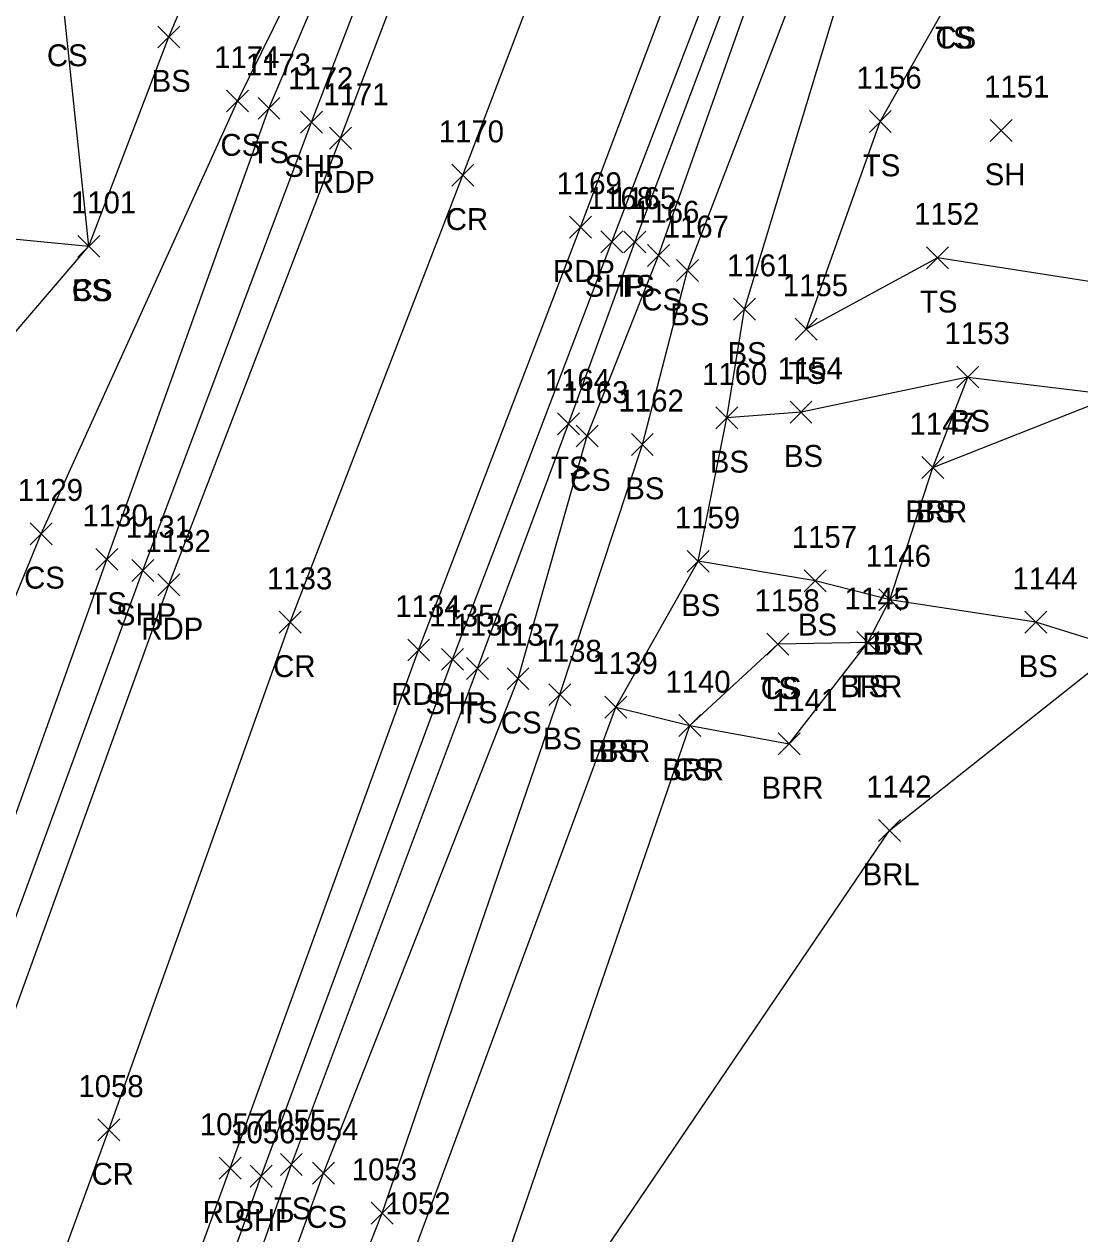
# Model space of a CAD drawing. Extents: x 1554917 to 1555870, y 813367 to 816333.
# Drawn here: x 1555006.4 to 1555102.6, y 813476.5 to 813586.9 of the extents above; entities that cross this region are included whole.
import ezdxf

# ---------------------------------------------------------------- set-up
doc = ezdxf.new("R2010")
doc.units = 0
for name, color, linetype in [('L_A', 7, 'Continuous'), ('L_I', 7, 'Continuous'), ('L_TIC', 7, 'Continuous'), ('LABL', 7, 'Continuous'), ('LELB', 7, 'Continuous'), ('P_A', 7, 'Continuous'), ('P_I', 7, 'Continuous'), ('P_TIC', 7, 'Continuous'), ('PET', 7, 'Continuous'), ('PRC', 7, 'Continuous'), ('PSP', 7, 'Continuous')]:
    doc.layers.add(name, color=color, linetype=linetype)

msp = doc.modelspace()

# ---------------------------------------------------------------- linework, layer by layer
at = {"layer": 'L_TIC'}
for points in [[(1555018.54, 813584.69), (1555020.54, 813586.69)], [(1555020.54, 813584.69), (1555018.54, 813586.69)], [(1555024.82, 813578.85), (1555026.82, 813580.85)], [(1555026.82, 813578.85), (1555024.82, 813580.85)], [(1555027.68, 813578.18), (1555029.68, 813580.18)], [(1555029.68, 813578.18), (1555027.68, 813580.18)], [(1555083.43, 813576.98), (1555085.43, 813578.98)], [(1555085.43, 813576.98), (1555083.43, 813578.98)], [(1555094.46, 813576.17), (1555096.46, 813578.17)], [(1555096.46, 813576.17), (1555094.46, 813578.17)], [(1555011.26, 813565.6), (1555013.26, 813567.6)], [(1555013.26, 813565.6), (1555011.26, 813567.6)], [(1555011.26, 813565.6), (1555013.26, 813567.6)], [(1555013.26, 813565.6), (1555011.26, 813567.6)], [(1555061.05, 813565.99), (1555063.05, 813567.99)], [(1555063.05, 813565.99), (1555061.05, 813567.99)], [(1555063.2, 813564.75), (1555065.2, 813566.75)], [(1555065.2, 813564.75), (1555063.2, 813566.75)], [(1555088.64, 813564.56), (1555090.64, 813566.56)], [(1555090.64, 813564.56), (1555088.64, 813566.56)], [(1555065.84, 813563.4), (1555067.84, 813565.4)], [(1555067.84, 813563.4), (1555065.84, 813565.4)], [(1555071.05, 813559.86), (1555073.05, 813561.86)], [(1555073.05, 813559.86), (1555071.05, 813561.86)], [(1555076.66, 813558.05), (1555078.66, 813560.05)], [(1555078.66, 813558.05), (1555076.66, 813560.05)], [(1555091.42, 813553.68), (1555093.42, 813555.68)], [(1555093.42, 813553.68), (1555091.42, 813555.68)], [(1555069.43, 813549.96), (1555071.43, 813551.96)], [(1555071.43, 813549.96), (1555069.43, 813551.96)], [(1555069.43, 813549.96), (1555071.43, 813551.96)], [(1555071.43, 813549.96), (1555069.43, 813551.96)], [(1555076.2, 813550.48), (1555078.2, 813552.48)], [(1555078.2, 813550.48), (1555076.2, 813552.48)], [(1555055, 813549.42), (1555057, 813551.42)], [(1555057, 813549.42), (1555055, 813551.42)], [(1555056.7, 813548.3), (1555058.7, 813550.3)], [(1555058.7, 813548.3), (1555056.7, 813550.3)], [(1555061.73, 813547.53), (1555063.73, 813549.53)], [(1555063.73, 813547.53), (1555061.73, 813549.53)], [(1555088.23, 813545.42), (1555090.23, 813547.42)], [(1555090.23, 813545.42), (1555088.23, 813547.42)], [(1555088.23, 813545.42), (1555090.23, 813547.42)], [(1555090.23, 813545.42), (1555088.23, 813547.42)], [(1555006.9, 813539.38), (1555008.9, 813541.38)], [(1555008.9, 813539.38), (1555006.9, 813541.38)], [(1555012.89, 813537.05), (1555014.89, 813539.05)], [(1555014.89, 813537.05), (1555012.89, 813539.05)], [(1555066.83, 813536.87), (1555068.83, 813538.87)], [(1555068.83, 813536.87), (1555066.83, 813538.87)], [(1555066.83, 813536.87), (1555068.83, 813538.87)], [(1555068.83, 813536.87), (1555066.83, 813538.87)], [(1555077.48, 813535.1), (1555079.48, 813537.1)], [(1555079.48, 813535.1), (1555077.48, 813537.1)], [(1555084.29, 813533.37), (1555086.29, 813535.37)], [(1555086.29, 813533.37), (1555084.29, 813535.37)], [(1555084.29, 813533.37), (1555086.29, 813535.37)], [(1555086.29, 813533.37), (1555084.29, 813535.37)], [(1555097.61, 813531.31), (1555099.61, 813533.31)], [(1555099.61, 813531.31), (1555097.61, 813533.31)], [(1555074.09, 813529.31), (1555076.09, 813531.31)], [(1555076.09, 813529.31), (1555074.09, 813531.31)], [(1555074.09, 813529.31), (1555076.09, 813531.31)], [(1555076.09, 813529.31), (1555074.09, 813531.31)], [(1555082.3, 813529.48), (1555084.3, 813531.48)], [(1555084.3, 813529.48), (1555082.3, 813531.48)], [(1555082.3, 813529.48), (1555084.3, 813531.48)], [(1555084.3, 813529.48), (1555082.3, 813531.48)], [(1555046.7, 813527.1), (1555048.7, 813529.1)], [(1555048.7, 813527.1), (1555046.7, 813529.1)], [(1555050.39, 813526.17), (1555052.39, 813528.17)], [(1555052.39, 813526.17), (1555050.39, 813528.17)], [(1555054.21, 813524.71), (1555056.21, 813526.71)], [(1555056.21, 813524.71), (1555054.21, 813526.71)], [(1555059.32, 813523.58), (1555061.32, 813525.58)], [(1555061.32, 813523.58), (1555059.32, 813525.58)], [(1555059.32, 813523.58), (1555061.32, 813525.58)], [(1555061.32, 813523.58), (1555059.32, 813525.58)], [(1555066.05, 813521.89), (1555068.05, 813523.89)], [(1555068.05, 813521.89), (1555066.05, 813523.89)], [(1555066.05, 813521.89), (1555068.05, 813523.89)], [(1555068.05, 813521.89), (1555066.05, 813523.89)], [(1555075.12, 813520.23), (1555077.12, 813522.23)], [(1555077.12, 813520.23), (1555075.12, 813522.23)], [(1555084.28, 813512.33), (1555086.28, 813514.33)], [(1555086.28, 813512.33), (1555084.28, 813514.33)], [(1555029.72, 813481.86), (1555031.72, 813483.86)], [(1555031.72, 813481.86), (1555029.72, 813483.86)], [(1555032.65, 813481.08), (1555034.65, 813483.08)], [(1555034.65, 813481.08), (1555032.65, 813483.08)], [(1555038.01, 813477.41), (1555040.01, 813479.41)], [(1555040.01, 813477.41), (1555038.01, 813479.41)]]:
    msp.add_lwpolyline(points, dxfattribs=at)
at = {"layer": 'LABL'}
for points in [[(1555021.43, 813420.92), (1555042.06, 813475.32), (1555060.32, 813524.58), (1555067.05, 813522.89), (1555076.12, 813521.23), (1555083.3, 813530.48), (1555085.29, 813534.37), (1555089.23, 813546.42), (1555105.94, 813553.01)], [(1555021.43, 813420.92), (1555032.42, 813420.89), (1555053.86, 813467), (1555085.28, 813513.33), (1555106.23, 813529.94), (1555105.94, 813553.01)]]:
    msp.add_lwpolyline(points, dxfattribs=at)
at = {"layer": 'LELB'}
for points in [[(1554960.86, 813387.22), (1554975.88, 813430.61), (1554997.67, 813492.71), (1555013.89, 813538.05), (1555028.68, 813579.18), (1555048.82, 813626.54), (1555068.18, 813674.18), (1555096.05, 813749.22), (1555111.01, 813785.1), (1555115.51, 813798.83), (1555119.3, 813812.87), (1555134.87, 813853.17), (1555141.95, 813870.8), (1555155.34, 813907.69), (1555153.32, 813917.67), (1555161.57, 813925.65), (1555168.92, 813938.89)], [(1554992.4, 813377.01), (1555009.62, 813423.34), (1555030.72, 813482.86), (1555047.7, 813528.1), (1555056, 813550.42), (1555062.05, 813566.99), (1555080.33, 813615.57), (1555099.41, 813662.25), (1555114.13, 813700.62), (1555127, 813733.84), (1555152.94, 813799.24), (1555168.16, 813840.25), (1555187.47, 813890.8), (1555199.5, 813919.6)], [(1554997.34, 813375.96), (1555001.03, 813380.2), (1555008.26, 813399.3), (1555016.85, 813422.36), (1555039.01, 813478.41), (1555055.21, 813525.71), (1555062.73, 813548.53), (1555066.84, 813564.4), (1555085.89, 813613.91), (1555101.8, 813661.36), (1555117.2, 813700.9), (1555129.69, 813732.82), (1555155.55, 813797.61), (1555171.4, 813838.65), (1555190.74, 813889.78), (1555201.42, 813914.42), (1555204.39, 813917.83), (1555206.44, 813916.94)], [(1555060.32, 813524.58), (1555067.83, 813537.87), (1555070.43, 813550.96), (1555072.05, 813560.86), (1555087.88, 813613.15), (1555106.35, 813658.95), (1555120.2, 813700.04), (1555133.19, 813731.1), (1555158.65, 813797.07), (1555174.38, 813837.99), (1555194.21, 813888.82), (1555206.44, 813916.94)], [(1554994.08, 813375.71), (1555012.26, 813423.24), (1555033.65, 813482.08), (1555051.39, 813527.17), (1555057.7, 813549.3), (1555064.2, 813565.75), (1555082.14, 813616.42), (1555099.41, 813662.25)], [(1554955.97, 813389.51), (1554961.01, 813406.77), (1554970.65, 813432.6), (1554989.8, 813496.28), (1555007.9, 813540.38), (1555025.82, 813579.85), (1555048.82, 813626.54)], [(1554928.52, 813569.72), (1554947.56, 813564.37), (1554964.46, 813556.66), (1554984.28, 813565), (1554997.17, 813568.08), (1555012.26, 813566.6), (1555009.99, 813588.02), (1555015.55, 813603.36), (1555029.3, 813621.81)], [(1555104.83, 813563.19), (1555089.64, 813565.56), (1555077.66, 813559.05), (1555084.43, 813577.98), (1555091.02, 813589.64), (1555101.22, 813603.84)], [(1554957.39, 813409.71), (1554960.72, 813434.3), (1554980.97, 813500.69), (1554989.73, 813523.17), (1554992.08, 813531.74), (1554995.75, 813541.57), (1554998.43, 813550.46), (1555012.26, 813566.6), (1555019.54, 813585.69), (1555024.77, 813597.99)], [(1555089.23, 813546.42), (1555092.42, 813554.68), (1555077.2, 813551.48), (1555070.43, 813550.96)], [(1555092.42, 813554.68), (1555105.94, 813553.01)], [(1555106.23, 813529.94), (1555098.61, 813532.31), (1555085.29, 813534.37), (1555078.48, 813536.1), (1555067.83, 813537.87)], [(1555004.95, 813373.58), (1555018.35, 813396.09), (1555032.42, 813420.89), (1555049, 813470.38), (1555067.05, 813522.89), (1555075.09, 813530.31)], [(1555083.3, 813530.48), (1555075.09, 813530.31)]]:
    msp.add_lwpolyline(points, dxfattribs=at)
at = {"layer": 'P_TIC'}
for points in [[(1555031.55, 813576.93), (1555033.55, 813578.93)], [(1555033.55, 813576.93), (1555031.55, 813578.93)], [(1555034.2, 813575.47), (1555036.2, 813577.47)], [(1555036.2, 813575.47), (1555034.2, 813577.47)], [(1555045.37, 813572.08), (1555047.37, 813574.08)], [(1555047.37, 813572.08), (1555045.37, 813574.08)], [(1555056.09, 813567.35), (1555058.09, 813569.35)], [(1555058.09, 813567.35), (1555056.09, 813569.35)], [(1555058.94, 813566), (1555060.94, 813568)], [(1555060.94, 813566), (1555058.94, 813568)], [(1555016.18, 813536.03), (1555018.18, 813538.03)], [(1555018.18, 813536.03), (1555016.18, 813538.03)], [(1555018.55, 813534.73), (1555020.55, 813536.73)], [(1555020.55, 813534.73), (1555018.55, 813536.73)], [(1555029.62, 813531.31), (1555031.62, 813533.31)], [(1555031.62, 813531.31), (1555029.62, 813533.31)], [(1555041.33, 813528.78), (1555043.33, 813530.78)], [(1555043.33, 813528.78), (1555041.33, 813530.78)], [(1555044.41, 813527.93), (1555046.41, 813529.93)], [(1555046.41, 813527.93), (1555044.41, 813529.93)], [(1555013.07, 813485.01), (1555015.07, 813487.01)], [(1555015.07, 813485.01), (1555013.07, 813487.01)], [(1555024.15, 813481.53), (1555026.15, 813483.53)], [(1555026.15, 813481.53), (1555024.15, 813483.53)], [(1555026.97, 813480.79), (1555028.97, 813482.79)], [(1555028.97, 813480.79), (1555026.97, 813482.79)]]:
    msp.add_lwpolyline(points, dxfattribs=at)
at = {"layer": 'PET'}
for points in [[(1554965.43, 813385.56), (1554980.95, 813429.92), (1555003.19, 813490.59), (1555019.55, 813535.73), (1555035.2, 813576.47), (1555053.52, 813624.76), (1555072.33, 813672.52), (1555101.11, 813747.71), (1555125.53, 813809.89), (1555141.72, 813851.12), (1555161.36, 813900.53), (1555183.5, 813956.99)], [(1554987.55, 813378.28), (1555004.34, 813425.43), (1555025.15, 813482.53), (1555042.33, 813529.78), (1555057.09, 813568.35), (1555075.57, 813617.35), (1555093.79, 813663.7), (1555108.49, 813702.81), (1555121.71, 813736.27), (1555147.41, 813801.52), (1555163.02, 813841.94), (1555182.57, 813892.25), (1555203.7, 813945.01)]]:
    msp.add_lwpolyline(points, dxfattribs=at)
at = {"layer": 'PRC'}
msp.add_lwpolyline([(1554976.76, 813382.18), (1554992.84, 813427.9), (1555014.07, 813486.01), (1555030.62, 813532.31), (1555046.37, 813573.08), (1555064.69, 813621.19), (1555082.41, 813667.53), (1555112.1, 813744.1), (1555110.69, 813739.79), (1555136.16, 813805.74), (1555152.52, 813846.93), (1555172.03, 813896.18), (1555193.96, 813951.2), (1555206.37, 813983.4), (1555218.13, 814013.22), (1555228.65, 814039.26), (1555237.93, 814064.31), (1555252.22, 814099.76), (1555265.8, 814135.89), (1555275.26, 814160.09), (1555297.17, 814214.77), (1555313.83, 814257.94), (1555329.72, 814298.26), (1555342.03, 814329.92)], dxfattribs=at)
at = {"layer": 'PSP'}
for points in [[(1554990.52, 813377.71), (1555007.26, 813424.1), (1555027.97, 813481.79), (1555045.41, 813528.93), (1555059.94, 813567), (1555096.82, 813663.08), (1555111.75, 813701.59), (1555124.82, 813734.75), (1555150.26, 813800.36), (1555166.19, 813840.91), (1555185.69, 813891.41), (1555197.67, 813922.42), (1555211.91, 813956.86)], [(1554963, 813386.3), (1554978.53, 813430.4), (1555000.44, 813491.39), (1555017.18, 813537.03), (1555032.55, 813577.93), (1555050.86, 813625.69), (1555069.49, 813673.81), (1555098.21, 813748.28), (1555122.69, 813810.6), (1555138.9, 813851.92), (1555160.79, 813906.47), (1555173.05, 813937.33)]]:
    msp.add_lwpolyline(points, dxfattribs=at)

# ---------------------------------------------------------------- texts
at = {"layer": 'L_A'}
for s, p in [('TS', (1555089.43, 813584.64)), ('CS', (1555089.46, 813584.64)), ('CS', (1555008.43, 813583.02)), ('BS', (1555017.98, 813580.69)), ('CS', (1555024.26, 813574.85)), ('TS', (1555027.09, 813574.18)), ('TS', (1555082.84, 813572.98)), ('SH', (1555093.95, 813572.17)), ('CS', (1555010.7, 813561.6)), ('BS', (1555010.7, 813561.6)), ('TS', (1555060.46, 813561.99)), ('CS', (1555062.64, 813560.75)), ('TS', (1555088.05, 813560.56)), ('BS', (1555065.28, 813559.4)), ('BS', (1555070.5, 813555.86)), ('TS', (1555076.07, 813554.05)), ('BS', (1555090.86, 813549.68)), ('BS', (1555068.88, 813545.96)), ('BS', (1555068.88, 813545.96)), ('BS', (1555075.64, 813546.48)), ('TS', (1555054.41, 813545.42)), ('CS', (1555056.14, 813544.3)), ('BS', (1555061.17, 813543.53)), ('BRR', (1555086.71, 813541.42)), ('BS', (1555087.67, 813541.42)), ('CS', (1555006.35, 813535.38)), ('TS', (1555012.3, 813533.05)), ('BS', (1555066.27, 813532.87)), ('BS', (1555066.27, 813532.87)), ('BS', (1555076.92, 813531.1)), ('BRR', (1555082.77, 813529.37)), ('BS', (1555083.73, 813529.37)), ('BS', (1555097.05, 813527.31)), ('TS', (1555073.5, 813525.31)), ('CS', (1555073.53, 813525.31)), ('BRR', (1555080.79, 813525.48)), ('TS', (1555081.71, 813525.48)), ('TS', (1555046.11, 813523.1)), ('CS', (1555049.83, 813522.17)), ('BS', (1555053.65, 813520.71)), ('BRR', (1555057.81, 813519.58)), ('BS', (1555058.77, 813519.58)), ('BRR', (1555064.53, 813517.89)), ('CS', (1555065.49, 813517.89)), ('BRR', (1555073.6, 813516.23)), ('BRL', (1555082.82, 813508.33)), ('TS', (1555029.13, 813477.86)), ('CS', (1555032.09, 813477.08))]:
    msp.add_text(s, height=2, dxfattribs=at).set_placement(p)
at = {"layer": 'L_I'}
for s, p in [('1174', (1555023.69, 813582.85)), ('1173', (1555026.56, 813582.18)), ('1156', (1555082.25, 813580.98)), ('1151', (1555093.9, 813580.17)), ('1165', (1555059.88, 813569.99)), ('1101', (1555010.62, 813569.6)), ('1101', (1555010.62, 813569.6)), ('1166', (1555061.98, 813568.75)), ('1152', (1555087.51, 813568.56)), ('1167', (1555064.67, 813567.4)), ('1161', (1555070.45, 813563.86)), ('1155', (1555075.54, 813562.05)), ('1153', (1555090.29, 813557.68)), ('1154', (1555075.07, 813554.48)), ('1164', (1555053.83, 813553.42)), ('1160', (1555068.18, 813553.96)), ('1160', (1555068.18, 813553.96)), ('1163', (1555055.52, 813552.3)), ('1162', (1555060.56, 813551.53)), ('1147', (1555087.1, 813549.42)), ('1147', (1555087.1, 813549.42)), ('1129', (1555005.77, 813543.38)), ('1130', (1555011.68, 813541.05)), ('1159', (1555065.7, 813540.87)), ('1159', (1555065.7, 813540.87)), ('1157', (1555076.36, 813539.1)), ('1146', (1555083.1, 813537.37)), ('1146', (1555083.1, 813537.37)), ('1144', (1555096.48, 813535.31)), ('1145', (1555081.17, 813533.48)), ('1145', (1555081.17, 813533.48)), ('1158', (1555072.96, 813533.31)), ('1158', (1555072.96, 813533.31)), ('1136', (1555045.52, 813531.1)), ('1137', (1555049.26, 813530.17)), ('1138', (1555053.08, 813528.71)), ('1139', (1555058.19, 813527.58)), ('1139', (1555058.19, 813527.58)), ('1140', (1555064.83, 813525.89)), ('1140', (1555064.83, 813525.89)), ('1141', (1555074.56, 813524.23)), ('1142', (1555083.15, 813516.33)), ('1055', (1555027.95, 813485.86)), ('1054', (1555030.88, 813485.08)), ('1053', (1555036.23, 813481.41)), ('1052', (1555039.29, 813478.32))]:
    msp.add_text(s, height=2, dxfattribs=at).set_placement(p)
at = {"layer": 'P_A'}
for s, p in [('SHP', (1555030.08, 813572.93)), ('RDP', (1555032.69, 813571.47)), ('CR', (1555044.8, 813568.08)), ('RDP', (1555054.58, 813563.35)), ('SHP', (1555057.47, 813562)), ('SHP', (1555014.72, 813532.03)), ('RDP', (1555017.04, 813530.73)), ('CR', (1555029.06, 813527.31)), ('RDP', (1555039.82, 813524.78)), ('SHP', (1555042.95, 813523.93)), ('CR', (1555012.5, 813481.01)), ('RDP', (1555022.64, 813477.53)), ('SHP', (1555025.51, 813476.79))]:
    msp.add_text(s, height=2, dxfattribs=at).set_placement(p)
at = {"layer": 'P_I'}
for s, p in [('1172', (1555030.42, 813580.93)), ('1171', (1555033.64, 813579.47)), ('1170', (1555044.16, 813576.08)), ('1169', (1555054.91, 813571.35)), ('1168', (1555057.76, 813570)), ('1131', (1555015.62, 813540.03)), ('1132', (1555017.42, 813538.73)), ('1133', (1555028.5, 813535.31)), ('1134', (1555040.2, 813532.78)), ('1135', (1555043.29, 813531.93)), ('1058', (1555011.3, 813489.01)), ('1057', (1555022.38, 813485.53)), ('1056', (1555025.15, 813484.79))]:
    msp.add_text(s, height=2, dxfattribs=at).set_placement(p)

doc.saveas('drawing.dxf')
